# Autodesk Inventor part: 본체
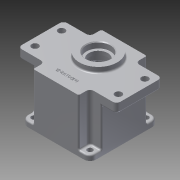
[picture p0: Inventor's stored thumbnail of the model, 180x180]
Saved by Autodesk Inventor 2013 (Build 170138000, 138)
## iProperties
Created: 2015-07
Part Number: 본체
Material: 알루미늄 6061
Document SubType Name: Modeling
Designer: user
Density: 1 g/cm^3
Author: user
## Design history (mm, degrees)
sketch "스케치1"
  geometry: L1 (-45, 45)-(45, 45); L2 (45, 45)-(45, -45); L3 (45, -45)-(-45, -45); L4 (-45, -45)-(-45, 45); 3 further points
  constraints: 8 end point, 2 midpoint, 2 parallel, 1 horizontal, 1 horizontal alignment, 1 perpendicular, 1 vertical alignment
  dimensions: "d0" = 90 distance of L2.end L3.end; "d1" = 90 distance of L1.end L2.end
extrude "돌출1" new body sketch "스케치1" distance "d2" = 70; taper "d3" = 0 deg
sketch "스케치2"
  geometry: L1 (-65, 30)-(65, 30); L2 (65, 30)-(65, -30); L3 (65, -30)-(-65, -30); L4 (-65, -30)-(-65, 30); 3 further points
  constraints: 8 end point, 2 midpoint, 2 parallel, 1 horizontal, 1 horizontal alignment, 1 perpendicular, 1 vertical alignment
  dimensions: "d4" = 130 distance of L2.end L3.end; "d5" = 60 distance of L1.end L2.end
extrude "돌출2" join sketch "스케치2" distance "d6" = 12; taper "d7" = 0 deg
sketch "스케치3"
  geometry: L1 (65, 30)-(65, -30) reference; L2 (45, 30)-(65, 30) reference; L3 (45, 30)-(45, 45) reference; L4 (45, 45)-(-45, 45) reference; L5 (-65, 30)-(-45, 30) reference; L6 (-65, -30)-(-65, 30) reference; L7 (30, 45)-(45, 45); L8 (45, 30)-(30, 30); L9 (30, 45)-(30, 30); L10 (45, 45)-(45, 30); L11 (-45, 45)-(-45, 30); L12 (-30, 45)-(-30, 30); L13 (-45, 30)-(-45, 45); L14 (-30, 45)-(-45, 45); L15 (-45, 30)-(-30, 30); L16 (-30, -45)-(-30, -30); L17 (-45, -30)-(-30, -30); L18 (-30, -45)-(-45, -45); L19 (-45, -45)-(-45, -30); L20 (-45, -45)-(-45, -30); L21 (-45, -30)-(-45, -45); L22 (45, -45)-(45, -30); L23 (45, -30)-(45, -45); L24 (30, -45)-(30, -30); L25 (45, -30)-(30, -30); L26 (30, -45)-(45, -45); L27 (-45, 45)-(-30, 45); L28 (30, 45)-(45, 45); 2 further points
  constraints: 44 end point, 4 parallel, 1 collinear, 1 perpendicular, 1 point on line
  dimensions: "d11" = 90 deg angle of L1 L28; "d12" = 90 deg angle of L1 L8; "d13" = 90 deg angle of L1 L25; "d14" = 90 deg angle of L1 L26; "d15" = 90 deg angle of L1 L15; "d16" = 90 deg angle of L1 L18; "d17" = 90 deg angle of L4 L9; "d18" = 90 deg angle of L4 L12; "d19" = 90 deg angle of L4 L13; "d20" = 90 deg angle of L4 L21; "d21" = 90 deg angle of L2 L22; "d22" = 90 deg angle of L2 L19; "d23" = 35 distance between parallel lines of L1 L24; "d24" = 95 distance between parallel lines of L1 L16; "d25" = 0 distance between parallel lines of L4 L27; "d26" = 75 distance from line of L1.start L26; "d27" = 35 distance from line of L1.start L9; "d28" = 95 distance from line of L1.start L12; "d29" = 75 distance from line of L1.start L18; "d30" = 20 distance from line of L28.end L1; "d31" = 20 distance from line of point (45, -45) L1; "d32" = 90 distance from line of point (45, -45) L4; "d33" = 90 distance from line of L19.start L4
extrude "돌출3" cut sketch "스케치3" distance "d34" = 63; taper "d35" = 0 deg
sketch "스케치4"
  geometry: L1 (65, 30)-(30, 30) reference; L2 (0, 0)-(0, 11); C1 r 25 at (0, 11)
  constraints: 2 end point, 1 centre point, 1 coincident, 1 perpendicular
  dimensions: "d36" = 11 distance of L2.start L2.end; "d37" = 25 radius of C1
extrude "돌출4" join sketch "스케치4" distance "d38" = 7; taper "d39" = 0 deg
sketch "스케치5"
  geometry: 1 further point
hole "구멍1" sketch "스케치5" at (0, 0) diameter "d40" = 78; stored, may be unused: countersink angle "d44" = 90 deg, drill point angle "d46" = 0 deg; dims "d41" = 6, "d42" = 80, "d43" = 9, "d45" = 61
sketch "스케치6"
  geometry: C1 r 25 at (0, 0) reference; 1 further point
hole "구멍2" sketch "스케치6" at (0, 0) diameter "d47" = 25; stored, may be unused: countersink angle "d51" = 90 deg, drill point angle "d53" = 0 deg; dims "d48" = 6, "d49" = 32, "d50" = 8, "d52" = 13
sketch "스케치9"
  geometry: C1 r 40 at (0, 0) reference; C2 r 39 at (0, 0) reference; A1 r 4 centre (-24.749, 24.749) between (-27.462, 21.809) and (-21.809, 27.462); A2 r 3.5 centre (-19.238, 29.836) between (-21.134, 32.777) and (-21.762, 27.412); A3 r 3.5 centre (-29.836, 19.238) between (-27.412, 21.762) and (-32.777, 21.134); A4 r 3.5 centre (-29.836, -19.238) between (-32.777, -21.134) and (-27.412, -21.762); A5 r 4 centre (-24.749, -24.749) between (-21.809, -27.462) and (-27.462, -21.809); A6 r 3.5 centre (-19.238, -29.836) between (-21.762, -27.412) and (-21.134, -32.777); A7 r 3.5 centre (19.238, -29.836) between (21.134, -32.777) and (21.762, -27.412); A8 r 4 centre (24.749, -24.749) between (27.462, -21.809) and (21.809, -27.462); A9 r 3.5 centre (29.836, -19.238) between (27.412, -21.762) and (32.777, -21.134); A10 r 3.5 centre (29.836, 19.238) between (32.777, 21.134) and (27.412, 21.762); A11 r 4 centre (24.749, 24.749) between (21.809, 27.462) and (27.462, 21.809); A12 r 3.5 centre (19.238, 29.836) between (21.762, 27.412) and (21.134, 32.777); A13 r 39 centre (0, 0) between (32.777, 21.134) and (21.134, 32.777); A14 r 39 centre (0, 0) between (-21.134, 32.777) and (-32.777, 21.134); A15 r 39 centre (0, 0) between (-32.777, -21.134) and (-21.134, -32.777); A16 r 39 centre (0, 0) between (21.134, -32.777) and (32.777, -21.134)
  constraints: 40 point on circle, 16 centre point, 5 tangent, 1 coincident, 49 other
  dimensions: "d71" = 4 radius of A1; "d72" = 3.5 radius of A2; "d73" = 3.5 radius of A3; "d76" = 360 deg dimension on C1.centre A2.centre (derived); "d78" = 39 radius of A16; "d79" = 35 distance of A10.end C2.centre; "d80" = 35 distance of A9.start C2.centre
extrude "돌출5" join sketch "스케치9" distance "d81" = 45; taper "d82" = 0 deg
sketch "스케치10"
  geometry: C1 r 39 at (0, 0) reference; A1 r 20.5 centre (0, 11) between (7.402, -8.117) and (-7.402, -8.117); A2 r 14 centre (0, -20) between (-7.402, -8.117) and (7.402, -8.117)
  constraints: 4 point on circle, 2 centre point
  dimensions: "d84" = 20.5 radius of A1; "d86" = 14 radius of A2; "d87" = 10.98533 distance of C1.centre A1.start; "d88" = 11 distance of C1.centre A1.centre; "d89" = 20 distance of C1.centre A2.centre
extrude "돌출6" join sketch "스케치10" distance "d90" = 7; taper "d91" = 0 deg
sketch "스케치11"
  geometry: A1 r 20.5 centre (0, 11) between (7.402, -8.117) and (-7.402, -8.117) reference; 1 further point
hole "구멍5" sketch "스케치11" at (0, 11) diameter "d92" = 35; stored, may be unused: countersink angle "d96" = 90 deg, drill point angle "d98" = 0 deg; dims "d93" = 6, "d94" = 22, "d95" = 7, "d97" = 10
sketch "스케치12"
  geometry: A1 r 14 centre (0, -20) between (-7.402, -8.117) and (7.402, -8.117) reference; 1 further point
hole "구멍6" sketch "스케치12" at (0, -20) diameter "d99" = 19; stored, may be unused: countersink angle "d103" = 90 deg, drill point angle "d105" = 0 deg; dims "d100" = 6, "d101" = 22, "d102" = 7, "d104" = 8
chamfer "모따기1" distance "d106" = 1; stored, may be unused: second distance "d107" = 2, angle "d108" = 45 deg
fillet "모깎기1" dims "d109" = 0.3
fillet "모깎기2" dims "d110" = 0.3
fillet "모깎기3" dims "d111" = 2
fillet "모깎기4" dims "d112" = 8
fillet "모깎기5" dims "d113" = 5
sketch "스케치13"
  geometry: L1 (-60, 30)-(30, 30) reference; L2 (0, 0)-(-55, 0); L3 (-55, 0)-(-55, -17.5); L4 (0, 0)-(0, -20.451); C1 r 4.5 at (-55, -17.5); C2 r 4.5 at (-55, 17.5); C3 r 4.5 at (55, -17.5); C4 r 4.5 at (55, 17.5); 1 further point
  constraints: 6 end point, 4 centre point, 3 symmetric about line, 2 parallel, 1 coincident, 1 perpendicular, 3 other
  dimensions: "d115" = 55 distance of L2.start L2.end; "d116" = 17.5 distance of L2.end L3.end; "d117" = 4.5 radius of C1
extrude "돌출7" cut sketch "스케치13" distance "d118" = 12; taper "d119" = 0 deg
sketch "스케치14"
  geometry: L1 (30, -30)-(30, -45) reference; L2 (37, -45)-(30, -45) reference; L3 (45, -30)-(45, -37) reference; L4 (45, -30)-(30, -30) reference; L5 (30, -45)-(-30, -45) reference; L6 (-30, -45)-(-30, -30) reference; L7 (-30, -30)-(-45, -30) reference; L8 (-45, -37)-(-45, -30) reference; L9 (-30, -45)-(-37, -45) reference; L10 (45, 30)-(45, -30) reference; L11 (30, 30)-(45, 30) reference; L12 (30, 45)-(30, 30) reference; L13 (30, 45)-(37, 45) reference; L14 (45, 37)-(45, 30) reference; L15 (-45, -30)-(-45, 30) reference; L16 (-45, 30)-(-30, 30) reference; L17 (-30, 30)-(-30, 45) reference; L18 (-37, 45)-(-30, 45) reference; L19 (-45, 30)-(-45, 37) reference; L20 (-30, 45)-(30, 45) reference; C1 r 40 at (0, 0) reference; A1 r 8 centre (37, 37) between (45, 37) and (37, 45) reference; A2 r 8 centre (37, -37) between (37, -45) and (45, -37) reference; A3 r 8 centre (-37, -37) between (-45, -37) and (-37, -45) reference; A4 r 8 centre (37, 37) between (45, 37) and (37, 45) reference; A5 r 8 centre (-37, 37) between (-37, 45) and (-45, 37) reference; 1 further point
hole "구멍7" sketch "스케치14" at (37, 37), (37, -37), (-37, -37), (-37, 37) diameter "d120" = 7; stored, may be unused: countersink angle "d124" = 90 deg, drill point angle "d126" = 0 deg; dims "d121" = 6, "d122" = 22, "d123" = 7, "d125" = 8
sketch "스케치15"
  geometry: A1 r 4 centre (-24.749, 24.749) between (-27.462, 21.809) and (-21.809, 27.462) reference; A2 r 4 centre (24.749, 24.749) between (21.809, 27.462) and (27.462, 21.809) reference; A3 r 4 centre (24.749, -24.749) between (27.462, -21.809) and (21.809, -27.462) reference; A4 r 4 centre (-24.749, -24.749) between (-21.809, -27.462) and (-27.462, -21.809) reference
hole "구멍8" sketch "스케치15" at (24.749, 24.749), (24.749, -24.749), (-24.749, -24.749), (-24.749, 24.749) diameter "d127" = 3.459; stored, may be unused: countersink angle "d131" = 90 deg, drill point angle "d133" = 118 deg; dims "d128" = 12, "d129" = 22, "d130" = 7, "d132" = 15
fillet "모깎기7" dims "d134" = 2
fillet "모깎기8" dims "d135" = 2
sketch "스케치17"
  geometry: L1 (-30, -45)-(30, -45) reference; L2 (-60, 30)-(-30, 30) reference; L3 (0, -45)-(0, -30); 2 further points
  constraints: 2 end point, 1 coincident, 1 midpoint, 1 perpendicular, 1 other
  dimensions: "d139" = 15 distance of L3.start L3.end
feature "엠보싱2" sketch "스케치17" dims "d0" = 90, "d1" = 90, "d140" = 0.5, "d141" = 0
fillet "모깎기10" dims "d143" = 2
fillet "모깎기11" dims "d144" = 2
fillet "모깎기12" dims "d145" = 2
fillet "모깎기13" dims "d146" = 2
fillet "모깎기14" dims "d147" = 2
fillet "모깎기15" dims "d148" = 2
fillet "모깎기16" dims "d149" = 5
node "솔리드1"
node "절단 모서리 투영1"
